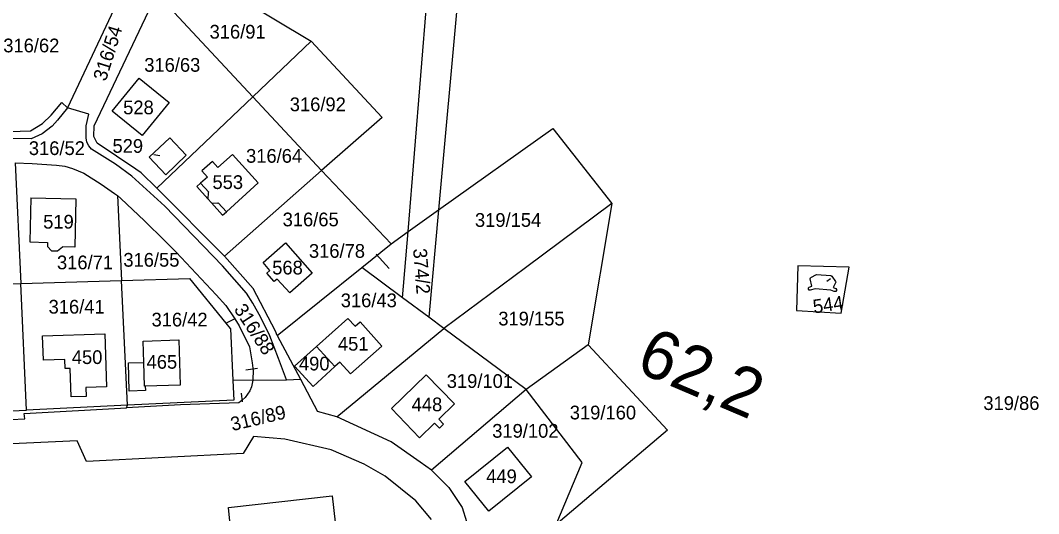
# Model space of a CAD drawing. Extents: x -805826 to -803822, y -1165880 to -1164382.
# Drawn here: x -805401.4 to -805148.9, y -1164843 to -1164720.9 of the extents above; entities that cross this region are included whole.
import ezdxf

# ---------------------------------------------------------------- set-up
doc = ezdxf.new("R2010")
doc.units = 0
for name, color, linetype in [('kilometráž - 2880', 7, 'Continuous'), ('kn_celek - Cisla parcel pomocna', 7, 'Continuous'), ('kn_celek - Cisla pozemkovych parcel', 7, 'Continuous'), ('kn_celek - Cisla stavebnich parcel', 7, 'Continuous'), ('kn_celek - Hranice parcel', 7, 'Continuous'), ('kn_celek - Vnitrni kresby', 7, 'Continuous')]:
    doc.layers.add(name, color=color, linetype=linetype)

msp = doc.modelspace()

# ---------------------------------------------------------------- linework, layer by layer
at = {"layer": 'kn_celek - Cisla parcel pomocna'}
for p, q in [((-805366.84, -1164754.4), (-805368.32, -1164754.16)), ((-805309.98, -1164782.35), (-805313.23, -1164778.79)), ((-805200.51, -1164784.85), (-805201.45, -1164785.55)), ((-805345.51, -1164807.42), (-805342.62, -1164806.97)), ((-805346.7, -1164813.19), (-805346.48, -1164815.33))]:
    msp.add_line(p, q, dxfattribs=at)
at = {"layer": 'kn_celek - Hranice parcel'}
for p, q in [((-805281.83, -1164592.37), (-805297.72, -1164767.78)), ((-805305.32, -1164773.18), (-805299.25, -1164699.31)), ((-805360.34, -1164707.4), (-805329.31, -1164726.02)), ((-805374.33, -1164709.68), (-805389.77, -1164742.48)), ((-805383.12, -1164747), (-805367.6, -1164714.25)), ((-805343.79, -1164739.78), (-805367.6, -1164714.25)), ((-805343.79, -1164739.78), (-805329.31, -1164726.02)), ((-805329.31, -1164726.02), (-805311.75, -1164744.88)), ((-805378.65, -1164743.34), (-805371.97, -1164735.14)), ((-805371.97, -1164735.14), (-805364.55, -1164741.18)), ((-805393.79, -1164744.35), (-805391.17, -1164741.17)), ((-805391.17, -1164741.17), (-805389.77, -1164742.48)), ((-805364.55, -1164741.18), (-805371.23, -1164749.37)), ((-805343.79, -1164739.78), (-805367.62, -1164762.38)), ((-805326.77, -1164758.06), (-805343.79, -1164739.78)), ((-805389.77, -1164742.48), (-805392.26, -1164745.6)), ((-805384.45, -1164744.08), (-805389.77, -1164742.48)), ((-805385.15, -1164746.99), (-805384.45, -1164744.08)), ((-805371.23, -1164749.37), (-805378.65, -1164743.34)), ((-805398.97, -1164748.23), (-805395.93, -1164746.42)), ((-805395.93, -1164746.42), (-805393.79, -1164744.35)), ((-805392.26, -1164745.6), (-805393.6, -1164747.05)), ((-805311.75, -1164744.88), (-805326.77, -1164758.06)), ((-805406.69, -1164748.5), (-805398.97, -1164748.23)), ((-805396.02, -1164748.95), (-805398.74, -1164750.19)), ((-805393.6, -1164747.05), (-805396.02, -1164748.95)), ((-805385.17, -1164749.99), (-805385.15, -1164746.99)), ((-805383.19, -1164749.61), (-805383.12, -1164747)), ((-805297.72, -1164767.78), (-805269.42, -1164747.67)), ((-805269.42, -1164747.67), (-805254.74, -1164766.2)), ((-805398.74, -1164750.19), (-805403.85, -1164750.15)), ((-805384.97, -1164751.03), (-805385.17, -1164749.99)), ((-805384.49, -1164751.92), (-805384.97, -1164751.03)), ((-805382.42, -1164751.24), (-805383.19, -1164749.61)), ((-805372.81, -1164757.75), (-805382.42, -1164751.24)), ((-805369.49, -1164754.72), (-805364.42, -1164749.92)), ((-805364.42, -1164749.92), (-805360.3, -1164754.26)), ((-805383.84, -1164752.73), (-805384.49, -1164751.92)), ((-805377.85, -1164756.51), (-805383.84, -1164752.73)), ((-805360.3, -1164754.26), (-805365.41, -1164759.1)), ((-805348.85, -1164754.06), (-805352.45, -1164757.31)), ((-805342.48, -1164761.13), (-805348.85, -1164754.06)), ((-805402.75, -1164756.18), (-805398.55, -1164756.29)), ((-805402.75, -1164756.18), (-805401.35, -1164786.02)), ((-805398.55, -1164756.29), (-805392.48, -1164756.74)), ((-805392.48, -1164756.74), (-805390.46, -1164757)), ((-805373.81, -1164759.47), (-805377.85, -1164756.51)), ((-805365.41, -1164759.1), (-805369.49, -1164754.72)), ((-805353.79, -1164755.82), (-805356.41, -1164758.16)), ((-805352.45, -1164757.31), (-805353.79, -1164755.82)), ((-805390.46, -1164757), (-805388.51, -1164757.54)), ((-805388.51, -1164757.54), (-805385.7, -1164758.69)), ((-805385.7, -1164758.69), (-805381.4, -1164761.41)), ((-805371.48, -1164758.62), (-805372.81, -1164757.75)), ((-805371.48, -1164758.62), (-805367.62, -1164762.38)), ((-805356.41, -1164758.16), (-805355.07, -1164759.68)), ((-805326.77, -1164758.06), (-805350.84, -1164779.27)), ((-805309.53, -1164776.18), (-805326.77, -1164758.06)), ((-805381.4, -1164761.41), (-805378.07, -1164763.73)), ((-805365.64, -1164766.91), (-805373.81, -1164759.47)), ((-805356.75, -1164761.17), (-805357.67, -1164762)), ((-805355.07, -1164759.68), (-805356.75, -1164761.17)), ((-805350.37, -1164768.24), (-805342.48, -1164761.13)), ((-805378.07, -1164763.73), (-805377.4, -1164764.27)), ((-805377.4, -1164764.27), (-805376.5, -1164765)), ((-805377.4, -1164764.27), (-805376.38, -1164785.32)), ((-805367.62, -1164762.38), (-805350.84, -1164779.27)), ((-805357.67, -1164762), (-805354.95, -1164765.04)), ((-805398.84, -1164764.83), (-805399.09, -1164775.74)), ((-805398.84, -1164764.83), (-805387.7, -1164765.07)), ((-805387.7, -1164765.07), (-805387.96, -1164777.01)), ((-805376.5, -1164765), (-805370.63, -1164770.52)), ((-805351.31, -1164781.67), (-805365.64, -1164766.91)), ((-805354.95, -1164765.04), (-805354.03, -1164766.08)), ((-805354.03, -1164766.08), (-805351.29, -1164769.07)), ((-805254.74, -1164766.2), (-805276.19, -1164782.12)), ((-805254.74, -1164766.2), (-805260.63, -1164801.21)), ((-805351.29, -1164769.07), (-805350.37, -1164768.24)), ((-805305.32, -1164773.18), (-805297.72, -1164767.78)), ((-805297.72, -1164767.78), (-805300.13, -1164794.4)), ((-805370.63, -1164770.52), (-805365.63, -1164775.45)), ((-805309.53, -1164776.18), (-805305.32, -1164773.18)), ((-805306.66, -1164789.57), (-805305.32, -1164773.18)), ((-805399.09, -1164775.74), (-805394.69, -1164775.84)), ((-805394.69, -1164775.84), (-805394.71, -1164776.85)), ((-805394.71, -1164776.85), (-805393.72, -1164777.93)), ((-805392.2, -1164777.97), (-805391.03, -1164776.95)), ((-805387.96, -1164777.01), (-805391.03, -1164776.95)), ((-805365.63, -1164775.45), (-805362.85, -1164778.31)), ((-805341.27, -1164780.83), (-805335.66, -1164775.98)), ((-805335.66, -1164775.98), (-805329.09, -1164783.49)), ((-805316.8, -1164782.07), (-805309.53, -1164776.18)), ((-805393.72, -1164777.93), (-805392.2, -1164777.97)), ((-805362.85, -1164778.31), (-805352.91, -1164788.82)), ((-805350.84, -1164779.27), (-805343.73, -1164787.3)), ((-805345.41, -1164788.39), (-805351.31, -1164781.67)), ((-805339.56, -1164782.79), (-805341.27, -1164780.83)), ((-805337.75, -1164798.93), (-805316.8, -1164782.07)), ((-805306.66, -1164789.57), (-805316.8, -1164782.07)), ((-805276.19, -1164782.12), (-805296.42, -1164797.15)), ((-805208.66, -1164781.62), (-805209, -1164792.76)), ((-805195.91, -1164782.02), (-805208.66, -1164781.62)), ((-805197.94, -1164793.35), (-805195.91, -1164782.02)), ((-805340.3, -1164783.45), (-805339.56, -1164782.79)), ((-805338.53, -1164785.51), (-805340.3, -1164783.45)), ((-805329.09, -1164783.49), (-805334.66, -1164788.38)), ((-805426.34, -1164786.82), (-805401.35, -1164786.02)), ((-805401.35, -1164786.02), (-805376.38, -1164785.32)), ((-805399.9, -1164817.43), (-805401.35, -1164786.02)), ((-805376.38, -1164785.32), (-805359.41, -1164784.83)), ((-805374.92, -1164816.2), (-805376.38, -1164785.32)), ((-805350.4, -1164795.9), (-805359.41, -1164784.83)), ((-805337.76, -1164784.92), (-805338.53, -1164785.51)), ((-805334.66, -1164788.38), (-805337.76, -1164784.92)), ((-805352.91, -1164788.82), (-805350.52, -1164791.47)), ((-805343.76, -1164790.87), (-805345.41, -1164788.39)), ((-805338.2, -1164797.84), (-805343.73, -1164787.3)), ((-805300.13, -1164794.4), (-805306.66, -1164789.57)), ((-805350.52, -1164791.47), (-805348.23, -1164794.82)), ((-805341.78, -1164794.43), (-805343.76, -1164790.87)), ((-805339.55, -1164798.98), (-805341.78, -1164794.43)), ((-805328.03, -1164801.62), (-805320.22, -1164794.67)), ((-805320.22, -1164794.67), (-805318.46, -1164796.64)), ((-805296.42, -1164797.15), (-805300.13, -1164794.4)), ((-805209, -1164792.76), (-805197.94, -1164793.35)), ((-805348.23, -1164794.82), (-805350.4, -1164795.9)), ((-805349.37, -1164797.17), (-805350.4, -1164795.9)), ((-805349.37, -1164797.17), (-805348.76, -1164810.06)), ((-805348.23, -1164794.82), (-805347.23, -1164796.52)), ((-805347.23, -1164796.52), (-805344.62, -1164801.75)), ((-805322.93, -1164819.08), (-805296.42, -1164797.15)), ((-805318.46, -1164796.64), (-805317.21, -1164795.51)), ((-805317.21, -1164795.51), (-805311.85, -1164801.54)), ((-805276.01, -1164812.3), (-805296.42, -1164797.15)), ((-805395.93, -1164799.04), (-805380.53, -1164798.51)), ((-805395.73, -1164805.06), (-805395.93, -1164799.04)), ((-805380.53, -1164798.51), (-805380.13, -1164811.65)), ((-805338.48, -1164801.78), (-805339.55, -1164798.98)), ((-805337.75, -1164798.93), (-805338.2, -1164797.84)), ((-805337.75, -1164798.93), (-805332.02, -1164809.7)), ((-805371.02, -1164800.31), (-805362.19, -1164799.99)), ((-805370.84, -1164805.57), (-805371.02, -1164800.31)), ((-805362.19, -1164799.99), (-805361.81, -1164811.19)), ((-805344.62, -1164801.75), (-805343.97, -1164805.7)), ((-805337.43, -1164804.63), (-805338.48, -1164801.78)), ((-805328.03, -1164801.62), (-805333.47, -1164806.48)), ((-805328.03, -1164801.62), (-805323.49, -1164806.63)), ((-805311.85, -1164801.54), (-805319.59, -1164808.44)), ((-805260.63, -1164801.21), (-805276.01, -1164812.3)), ((-805260.63, -1164801.21), (-805240.99, -1164822.34)), ((-805390.4, -1164804.88), (-805395.73, -1164805.06)), ((-805390.32, -1164807.09), (-805390.4, -1164804.88)), ((-805335.48, -1164809.9), (-805337.43, -1164804.63)), ((-805389.12, -1164807.06), (-805390.32, -1164807.09)), ((-805388.88, -1164814.11), (-805389.12, -1164807.06)), ((-805374.63, -1164805.69), (-805370.84, -1164805.57)), ((-805374.43, -1164812.69), (-805374.63, -1164805.69)), ((-805343.97, -1164805.7), (-805343.74, -1164807.7)), ((-805333.47, -1164806.48), (-805328.8, -1164811.51)), ((-805328.8, -1164811.51), (-805323.49, -1164806.63)), ((-805322.22, -1164805.49), (-805323.49, -1164806.63)), ((-805319.59, -1164808.44), (-805322.22, -1164805.49)), ((-805343.74, -1164807.7), (-805343.77, -1164809.71)), ((-805343.77, -1164809.71), (-805343.77, -1164810.01)), ((-805343.77, -1164810.01), (-805335.48, -1164809.9)), ((-805335.48, -1164809.9), (-805332.02, -1164809.7)), ((-805332.02, -1164809.7), (-805327.75, -1164817.74)), ((-805309.42, -1164817), (-805300.8, -1164808.64)), ((-805300.8, -1164808.64), (-805293.82, -1164815.88)), ((-805380.13, -1164811.65), (-805385.22, -1164811.82)), ((-805385.22, -1164811.82), (-805385.14, -1164813.99)), ((-805361.81, -1164811.19), (-805370.46, -1164811.46)), ((-805370.46, -1164811.46), (-805370.44, -1164812.55)), ((-805343.77, -1164810.01), (-805348.76, -1164810.06)), ((-805348.76, -1164810.06), (-805348.52, -1164814.97)), ((-805344.14, -1164811.67), (-805344.54, -1164812.61)), ((-805343.77, -1164810.01), (-805344.14, -1164811.67)), ((-805276.01, -1164812.3), (-805299.48, -1164832.25)), ((-805262.09, -1164830.37), (-805276.01, -1164812.3)), ((-805385.14, -1164813.99), (-805388.88, -1164814.11)), ((-805348.52, -1164814.97), (-805374.92, -1164816.2)), ((-805370.44, -1164812.55), (-805374.43, -1164812.69)), ((-805346.47, -1164814.97), (-805347.25, -1164815.61)), ((-805345.73, -1164814.25), (-805346.47, -1164814.97)), ((-805345.09, -1164813.49), (-805345.73, -1164814.25)), ((-805344.54, -1164812.61), (-805345.09, -1164813.49)), ((-805424.87, -1164818.65), (-805399.9, -1164817.43)), ((-805400.52, -1164818.21), (-805375.12, -1164816.81)), ((-805374.92, -1164816.2), (-805399.9, -1164817.43)), ((-805361.72, -1164816.13), (-805375.12, -1164816.81)), ((-805375.12, -1164816.81), (-805374.92, -1164816.2)), ((-805347.25, -1164815.61), (-805361.72, -1164816.13)), ((-805302.45, -1164824.28), (-805309.42, -1164817)), ((-805293.82, -1164815.88), (-805297.7, -1164819.66)), ((-805426.66, -1164820.85), (-805400.32, -1164819.59)), ((-805400.32, -1164819.59), (-805400.52, -1164818.21)), ((-805322.93, -1164819.08), (-805327.75, -1164817.74)), ((-805309.46, -1164825.23), (-805322.93, -1164819.08)), ((-805297.7, -1164819.66), (-805296.53, -1164820.88)), ((-805298.71, -1164820.63), (-805302.45, -1164824.28)), ((-805297.53, -1164821.85), (-805298.71, -1164820.63)), ((-805296.53, -1164820.88), (-805297.53, -1164821.85)), ((-805240.99, -1164822.34), (-805268.57, -1164845.77)), ((-805387.37, -1164825.01), (-805451.24, -1164827.98)), ((-805385.06, -1164830.14), (-805387.37, -1164825.01)), ((-805343.67, -1164823.94), (-805346.18, -1164828.15)), ((-805335.85, -1164824.62), (-805343.67, -1164823.94)), ((-805324.4, -1164827.28), (-805335.85, -1164824.62)), ((-805316.21, -1164830.83), (-805324.4, -1164827.28)), ((-805302.28, -1164830.31), (-805309.46, -1164825.23)), ((-805291.19, -1164835.1), (-805280.62, -1164826.54)), ((-805280.62, -1164826.54), (-805274.7, -1164833.89)), ((-805346.18, -1164828.15), (-805385.06, -1164830.14)), ((-805311.02, -1164833.75), (-805316.21, -1164830.83)), ((-805299.48, -1164832.25), (-805302.28, -1164830.31)), ((-805299.48, -1164832.25), (-805295.19, -1164836.56)), ((-805268.57, -1164845.77), (-805262.09, -1164830.37)), ((-805303.36, -1164839.88), (-805311.02, -1164833.75)), ((-805285.29, -1164842.44), (-805291.19, -1164835.1)), ((-805274.7, -1164833.89), (-805285.29, -1164842.44)), ((-805295.19, -1164836.56), (-805291.92, -1164841.55)), ((-805349.86, -1164841.51), (-805324.16, -1164838.62)), ((-805324.16, -1164838.62), (-805322.87, -1164849.93)), ((-805299.51, -1164844.46), (-805303.36, -1164839.88)), ((-805349.4, -1164845.7), (-805349.86, -1164841.51)), ((-805291.92, -1164841.55), (-805289.74, -1164848.48))]:
    msp.add_line(p, q, dxfattribs=at)
at = {"layer": 'kn_celek - Vnitrni kresby'}
for p, q in [((-805356.75, -1164761.17), (-805354.73, -1164763.4)), ((-805354.89, -1164763.54), (-805354.95, -1164765.04)), ((-805354.73, -1164763.4), (-805354.89, -1164763.54)), ((-805354.03, -1164766.08), (-805352.54, -1164766.15)), ((-805352.54, -1164766.15), (-805352.38, -1164766.02)), ((-805352.38, -1164766.02), (-805350.37, -1164768.24)), ((-805205.61, -1164784.84), (-805205.53, -1164784.67)), ((-805205.53, -1164784.67), (-805205.42, -1164784.52)), ((-805205.42, -1164784.52), (-805204.01, -1164783.84)), ((-805204.01, -1164783.84), (-805200.43, -1164784.08)), ((-805200.43, -1164784.08), (-805200.22, -1164784.2)), ((-805200.22, -1164784.2), (-805199.29, -1164785.51)), ((-805206.04, -1164787.43), (-805206.01, -1164787.11)), ((-805206.01, -1164787.11), (-805205.82, -1164786.92)), ((-805205.82, -1164786.92), (-805205.18, -1164786.69)), ((-805205.18, -1164786.69), (-805205.61, -1164784.84)), ((-805199.28, -1164785.89), (-805199.85, -1164787)), ((-805199.85, -1164787), (-805199.2, -1164787.31)), ((-805199.29, -1164785.51), (-805199.23, -1164785.73)), ((-805199.23, -1164785.73), (-805199.28, -1164785.89)), ((-805205.86, -1164787.65), (-805206.04, -1164787.43)), ((-805205.58, -1164787.7), (-805205.86, -1164787.65)), ((-805204.38, -1164787.39), (-805205.58, -1164787.7)), ((-805200.5, -1164787.67), (-805204.38, -1164787.39)), ((-805199.6, -1164788.04), (-805200.5, -1164787.67)), ((-805199.24, -1164788.05), (-805199.6, -1164788.04)), ((-805199.07, -1164787.78), (-805199.24, -1164788.05)), ((-805199.2, -1164787.31), (-805199.04, -1164787.53)), ((-805199.04, -1164787.53), (-805199.07, -1164787.78)), ((-805370.63, -1164811.47), (-805370.84, -1164805.57)), ((-805370.46, -1164811.46), (-805370.63, -1164811.47))]:
    msp.add_line(p, q, dxfattribs=at)

# ---------------------------------------------------------------- texts
at = {"layer": 'kilometráž - 2880'}
msp.add_text('62,2', height=12, rotation=337.0034, dxfattribs=at).set_placement((-805249.23, -1164807.59))
at = {"layer": 'kn_celek - Cisla parcel pomocna'}
for s, p in [('529', (-805378.6, -1164753.66)), ('316/78', (-805329.89, -1164779.67))]:
    msp.add_text(s, height=3.4, dxfattribs=at).set_placement(p)
for s, rotation, p in [('544', 8.253, (-805204.66, -1164793.47)), ('316/88', 303.093, (-805348.61, -1164792.44)), ('316/89', 13.293, (-805348.88, -1164822.61))]:
    msp.add_text(s, height=3.4, rotation=rotation, dxfattribs=at).set_placement(p)
at = {"layer": 'kn_celek - Cisla pozemkovych parcel'}
for s, rotation, p in [('316/54', 72.765, (-805380.24, -1164736.1)), ('374/2', 274.563, (-805304.07, -1164777.46))]:
    msp.add_text(s, height=3.4, rotation=rotation, dxfattribs=at).set_placement(p)
for s, height, p in [('316/91', 3.4, (-805354.53, -1164725.37)), ('316/62', 3.4, (-805405.69, -1164728.77)), ('316/63', 3.4, (-805370.73, -1164733.58)), ('316/92', 3.4, (-805334.64, -1164743.35)), ('316/52', 3.4, (-805399.35, -1164754.21)), ('316/64', 3.4, (-805345.48, -1164756.12)), ('316/65', 3.4, (-805336.41, -1164771.87)), ('319/154', 3.4, (-805288.72, -1164772)), ('316/71', 3.4, (-805392.37, -1164782.51)), ('316/55', 3.4, (-805375.91, -1164781.87)), ('316/78', 0.005, (-805309.98, -1164782.35)), ('316/43', 3.4, (-805322, -1164791.91)), ('316/41', 3.4, (-805394.45, -1164793.49)), ('316/42', 3.4, (-805368.92, -1164796.68)), ('319/155', 3.4, (-805282.93, -1164796.43)), ('316/88', 0.005, (-805345.51, -1164807.42)), ('319/101', 3.4, (-805295.71, -1164811.9)), ('316/89', 0.005, (-805346.7, -1164813.19)), ('319/86', 3.4, (-805162.64, -1164817.37)), ('319/160', 3.4, (-805265.2, -1164819.7)), ('319/102', 3.4, (-805284.44, -1164824.24))]:
    msp.add_text(s, height=height, dxfattribs=at).set_placement(p)
at = {"layer": 'kn_celek - Cisla stavebnich parcel'}
for s, height, p in [('528', 3.4, (-805375.96, -1164744.12)), ('529', 0.005, (-805366.84, -1164754.4)), ('553', 3.4, (-805353.81, -1164762.63)), ('519', 3.4, (-805395.79, -1164772.43)), ('568', 3.4, (-805338.99, -1164783.79)), ('544', 0.005, (-805200.51, -1164784.85)), ('451', 3.4, (-805322.7, -1164802.67)), ('450', 3.4, (-805388.69, -1164805.98)), ('465', 3.4, (-805370.15, -1164807.15)), ('490', 3.4, (-805332.36, -1164807.57)), ('448', 3.4, (-805304.42, -1164817.69)), ('449', 3.4, (-805285.93, -1164835.49))]:
    msp.add_text(s, height=height, dxfattribs=at).set_placement(p)

doc.saveas('drawing.dxf')
